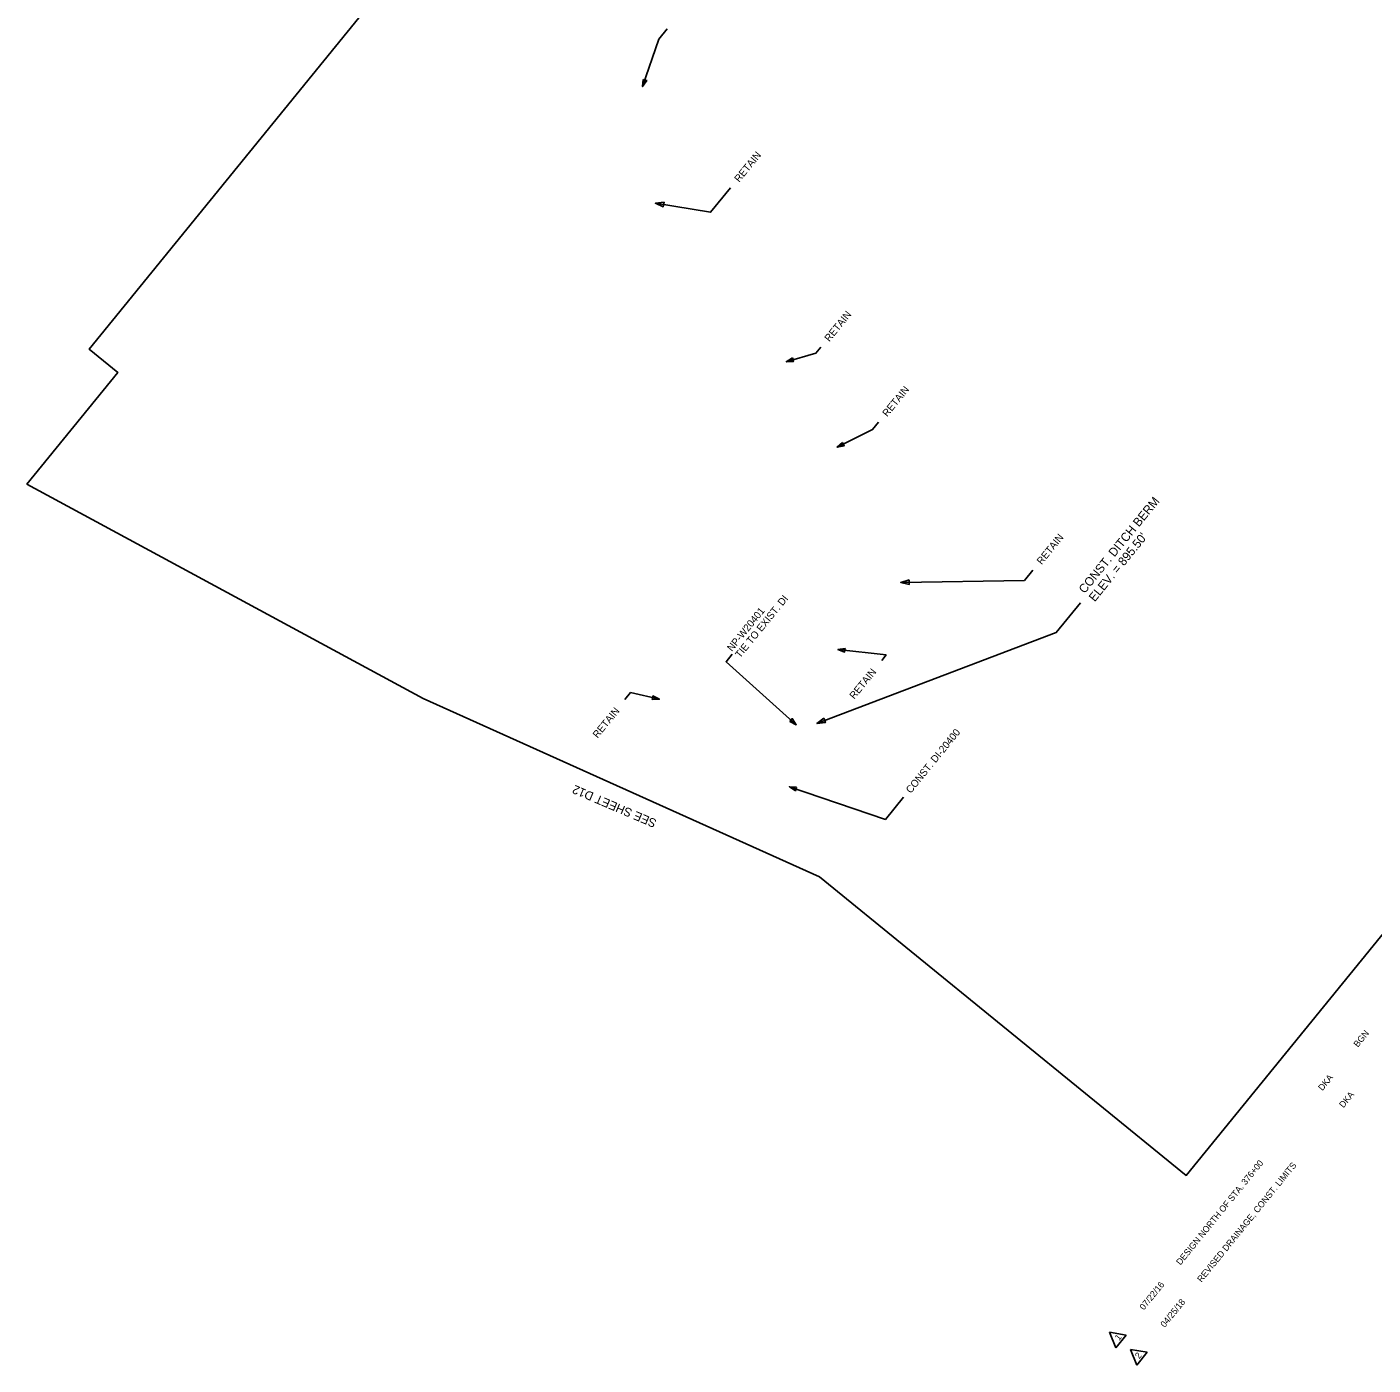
# Model space of a CAD drawing. Extents: x 1615497 to 1617608, y 1099429 to 1101318.
# Drawn here: x 1615822 to 1616750, y 1099429 to 1100352 of the extents above; entities that cross this region are included whole.
import ezdxf

# ---------------------------------------------------------------- set-up
doc = ezdxf.new("R2010")
doc.units = 0
for name, color, linetype in [('RD_EX_Misc', 7, 'Continuous'), ('RD_EX_Misc_txCode', 7, 'Continuous'), ('RD_HC_Data_Rel', 7, 'Continuous'), ('RD_PD_Final_TrvlWay', 7, 'Continuous')]:
    doc.layers.add(name, color=color, linetype=linetype)

msp = doc.modelspace()

# ---------------------------------------------------------------- linework, layer by layer
at = {"layer": 'RD_EX_Misc'}
msp.add_lwpolyline([(1616368.69, 1099765.81), (1616621.58, 1099559.95), (1617489.21, 1100625.83), (1617256.2, 1100856.12), (1617080.14, 1101099.03), (1616848.93, 1101284.68), (1616739.09, 1101147.89), (1616711.26, 1101170.24), (1615864.95, 1100129.78), (1615884.56, 1100113.83), (1615821.92, 1100036.83), (1616095.11, 1099888.91)], close=True, dxfattribs=at)
msp.add_lwpolyline([(1616368.69, 1099765.81), (1616621.58, 1099559.95), (1617489.21, 1100625.83), (1617256.2, 1100856.12), (1617080.14, 1101099.03), (1616848.93, 1101284.68), (1616739.09, 1101147.89), (1616711.26, 1101170.24), (1615864.95, 1100129.78), (1615884.56, 1100113.83), (1615821.92, 1100036.83), (1616095.11, 1099888.91)], close=True, dxfattribs=at)
msp.add_lwpolyline([(1616368.69, 1099765.81), (1616621.58, 1099559.95), (1617489.21, 1100625.83), (1617256.2, 1100856.12), (1617080.14, 1101099.03), (1616848.93, 1101284.68), (1616739.09, 1101147.89), (1616711.26, 1101170.24), (1615864.95, 1100129.78), (1615884.56, 1100113.83), (1615821.92, 1100036.83), (1616095.11, 1099888.91)], close=True, dxfattribs=at)
msp.add_lwpolyline([(1616368.69, 1099765.81), (1616621.58, 1099559.95), (1617489.21, 1100625.83), (1617256.2, 1100856.12), (1617080.14, 1101099.03), (1616848.93, 1101284.68), (1616739.09, 1101147.89), (1616711.26, 1101170.24), (1615864.95, 1100129.78), (1615884.56, 1100113.83), (1615821.92, 1100036.83), (1616095.11, 1099888.91)], close=True, dxfattribs=at)
msp.add_lwpolyline([(1616368.69, 1099765.81), (1616621.58, 1099559.95), (1617489.21, 1100625.83), (1617256.2, 1100856.12), (1617080.14, 1101099.03), (1616848.93, 1101284.68), (1616739.09, 1101147.89), (1616711.26, 1101170.24), (1615864.95, 1100129.78), (1615884.56, 1100113.83), (1615821.92, 1100036.83), (1616095.11, 1099888.91)], close=True, dxfattribs=at)
at = {"layer": 'RD_EX_Misc_txCode'}
for p, q in [((1616580.05, 1099449.74), (1616568.58, 1099451.73)), ((1616568.58, 1099451.73), (1616572.86, 1099440.91)), ((1616572.86, 1099440.91), (1616580.05, 1099449.74)), ((1616594.55, 1099437.94), (1616583.08, 1099439.93)), ((1616583.08, 1099439.93), (1616587.36, 1099429.1)), ((1616587.36, 1099429.1), (1616594.55, 1099437.94))]:
    msp.add_line(p, q, dxfattribs=at)
at = {"layer": 'RD_HC_Data_Rel'}
for points in [[(1616263.58, 1100350.79), (1616257.8, 1100343.69), (1616246.61, 1100310.98)], [(1616307.2, 1100241.18), (1616293.49, 1100224.34), (1616255.38, 1100230.56)], [(1616369.39, 1100131.21), (1616366.07, 1100127.15), (1616345.63, 1100121.24)], [(1616409.29, 1100079.46), (1616405.21, 1100074.44), (1616380.75, 1100062.29)], [(1616515.78, 1099977.47), (1616509.87, 1099970.2), (1616424.65, 1099969.02)], [(1616548.54, 1099954.95), (1616531.91, 1099934.53), (1616366.75, 1099871.74)], [(1616411.49, 1099915.2), (1616414.52, 1099918.93), (1616381.25, 1099922.7)], [(1616308.43, 1099919.51), (1616304.15, 1099914.25), (1616352.55, 1099870.81)], [(1616234.4, 1099888.3), (1616238.22, 1099893), (1616258.12, 1099888.35)], [(1616426.44, 1099820.78), (1616414.04, 1099805.54), (1616347.8, 1099828.03)]]:
    msp.add_lwpolyline(points, dxfattribs=at)
for points in [[(1616246.95, 1100315.97), (1616246.61, 1100310.98), (1616249.4, 1100315.14)], [(1616261.35, 1100231.16), (1616255.38, 1100230.56), (1616260.85, 1100228.09)], [(1616349.91, 1100123.83), (1616345.63, 1100121.24), (1616350.63, 1100121.34)], [(1616384.5, 1100065.59), (1616380.75, 1100062.29), (1616385.65, 1100063.28)], [(1616430.42, 1099970.65), (1616424.65, 1099969.02), (1616430.46, 1099967.55)], [(1616386.2, 1099923.44), (1616381.25, 1099922.7), (1616385.9, 1099920.87)], [(1616253.12, 1099888.19), (1616258.12, 1099888.35), (1616253.71, 1099890.71)], [(1616348.09, 1099873.08), (1616352.55, 1099870.81), (1616349.82, 1099875)], [(1616371.61, 1099875.26), (1616366.75, 1099871.74), (1616372.71, 1099872.35)], [(1616352.79, 1099827.71), (1616347.8, 1099828.03), (1616351.96, 1099825.26)]]:
    msp.add_lwpolyline(points, close=True, dxfattribs=at)

# ---------------------------------------------------------------- texts
at = {"layer": 'RD_EX_Misc_txCode'}
for s, p in [('BGN', (1616739.89, 1099648)), ('DKA', (1616715.47, 1099617.99)), ('DKA', (1616729.97, 1099606.19)), ('DESIGN NORTH OF STA. 376+00', (1616617.55, 1099497.69)), ('REVISED DRAINAGE, CONST. LIMITS', (1616632.05, 1099485.88)), ('07/22/16', (1616592.31, 1099466.68)), ('04/25/18', (1616606.7, 1099454.73)), ('1', (1616575.2, 1099445.66)), ('2', (1616589.09, 1099433.1))]:
    msp.add_text(s, height=4.4, rotation=50.85614, dxfattribs=at).set_placement(p)
at = {"layer": 'RD_HC_Data_Rel'}
for s, height, p in [('RETAIN', 5, (1616313.21, 1100244.61)), ('RETAIN', 5, (1616375.4, 1100134.64)), ('RETAIN', 5, (1616415.3, 1100082.88)), ('CONST. DITCH BERM', 6, (1616551.45, 1099960.9)), ("ELEV. = 895.50'", 6, (1616558.43, 1099955.22)), ('RETAIN', 5, (1616521.79, 1099980.89)), ('TIE TO EXIST. DI', 5, (1616313.79, 1099916.43)), ('NP-W20401', 5, (1616308.2, 1099920.98)), ('RETAIN', 5, (1616392.62, 1099888.07)), ('RETAIN', 5, (1616215.54, 1099861.17)), ('CONST. DI-20400', 5, (1616431.54, 1099823.08))]:
    msp.add_text(s, height=height, rotation=50.85452, dxfattribs=at).set_placement(p)
at = {"layer": 'RD_PD_Final_TrvlWay'}
msp.add_text('SEE SHEET D12', height=6, rotation=156.8359, dxfattribs=at).set_placement((1616256.8, 1099805.04))

doc.saveas('drawing.dxf')
